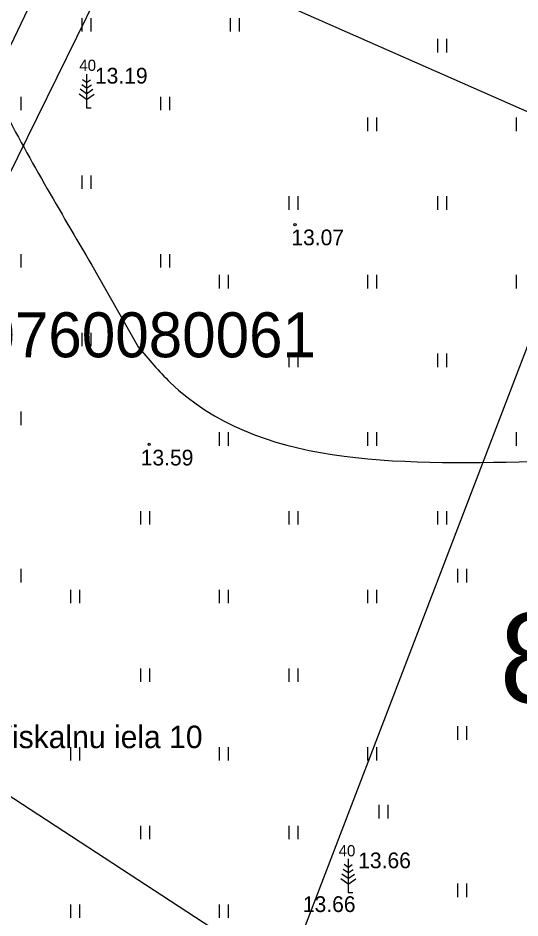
# Model space of a CAD drawing. Extents: x 503877 to 504025, y 304562 to 304725.
# Drawn here: x 503952.92 to 503975.24, y 304618.66 to 304658.69 of the extents above; entities that cross this region are included whole.
import ezdxf

# ---------------------------------------------------------------- set-up
doc = ezdxf.new("R2010")
doc.units = 0
for name, color, linetype in [('24', 7, 'Continuous'), ('APGS_VADP_ZSPR_####_#', 7, 'Continuous'), ('BUVE_EKAS_ADRS_TKST_#', 7, 'Continuous'), ('Level 1', 7, 'Continuous'), ('Level 46', 7, 'Continuous'), ('RELJ_AATZ_####_TKST_#', 7, 'Continuous'), ('RELJ_ELEM_####_####_#', 7, 'Continuous'), ('RELJ_HORZ_PAMT_####_#', 7, 'Continuous'), ('TERT_DIAM_####_TKST_#', 7, 'Continuous'), ('TERT_ELEM_####_####_#', 7, 'Continuous')]:
    doc.layers.add(name, color=color, linetype=linetype)

msp = doc.modelspace()

# ---------------------------------------------------------------- linework, layer by layer
at = {"layer": '24'}
for p, q in [((503952.592, 304664.678), (503978.978, 304653.014)), ((503978.978, 304653.014), (503960.823, 304605.633))]:
    msp.add_line(p, q, dxfattribs=at)
at = {"layer": 'APGS_VADP_ZSPR_####_#'}
msp.add_lwpolyline([(503962.091, 304677.36), (503950.94, 304654.055), (503950.749, 304653.94), (503947.69, 304653.253), (503947.598, 304653.154), (503939.904, 304637.662)], dxfattribs=at)
at = {"layer": 'Level 1'}
for p, q in [((503967.6, 304620.911), (503967.562, 304620.939)), ((503967.6, 304621.053), (503967.6, 304619.787)), ((503967.6, 304620.911), (503967.774, 304621.039)), ((503967.6, 304620.411), (503967.427, 304620.538)), ((503967.6, 304620.661), (503967.494, 304620.738)), ((503967.6, 304620.661), (503967.816, 304620.819)), ((503967.6, 304620.411), (503967.878, 304620.615)), ((503967.6, 304620.161), (503967.36, 304620.338)), ((503967.6, 304620.161), (503967.934, 304620.405)), ((503967.6, 304619.787), (503967.8, 304619.787))]:
    msp.add_line(p, q, dxfattribs=at)
at = {"layer": 'Level 46'}
msp.add_line((503980.064, 304707.607), (503941.479, 304629.359), dxfattribs=at)
at = {"layer": 'RELJ_ELEM_####_####_#'}
for centre in [(503965.239, 304649.497), (503958.753, 304639.733)]:
    msp.add_circle(centre, 0.05, dxfattribs=at)
at = {"layer": 'RELJ_HORZ_PAMT_####_#'}
for p, q in [((503956.212, 304647.7), (503958.259, 304644.072)), ((503966.227, 304615.164), (503949.188, 304626.264))]:
    msp.add_line(p, q, dxfattribs=at)
for points in [[(503952.816, 304672.072), (503952.987, 304664.738), (503952.905, 304663.502), (503952.654, 304662.245), (503952.49, 304661.612), (503952.312, 304660.984), (503952.133, 304660.355), (503951.965, 304659.719), (503951.712, 304658.5), (503951.624, 304657.887), (503951.562, 304657.273), (503951.573, 304656.693), (503951.668, 304656.113), (503951.833, 304655.556), (503952.085, 304655.015), (503956.212, 304647.7)], [(503958.259, 304644.072), (503959.691, 304642.482), (503975.774, 304638.957)]]:
    msp.add_spline(points, degree=3, dxfattribs=at)
at = {"layer": 'TERT_ELEM_####_####_#'}
for p, q in [((503955.771, 304658.087), (503955.771, 304658.687)), ((503956.171, 304658.087), (503956.171, 304658.687)), ((503962.371, 304658.087), (503962.371, 304658.687)), ((503962.771, 304658.087), (503962.771, 304658.687)), ((503971.579, 304657.162), (503971.579, 304657.762)), ((503971.979, 304657.162), (503971.979, 304657.762)), ((503955.97, 304656.192), (503955.97, 304654.692)), ((503955.97, 304655.566), (503955.754, 304655.724)), ((503955.97, 304655.816), (503955.794, 304655.944)), ((503955.97, 304655.816), (503956.144, 304655.944)), ((503955.97, 304655.566), (503956.186, 304655.724)), ((503955.97, 304655.066), (503955.638, 304655.31)), ((503955.97, 304655.316), (503955.692, 304655.52)), ((503955.97, 304655.316), (503956.248, 304655.52)), ((503955.97, 304655.066), (503956.304, 304655.31)), ((503953.071, 304654.587), (503953.071, 304655.187)), ((503959.271, 304654.587), (503959.271, 304655.187)), ((503959.671, 304654.587), (503959.671, 304655.187)), ((503955.97, 304654.692), (503956.17, 304654.692)), ((503968.479, 304653.662), (503968.479, 304654.262)), ((503968.879, 304653.662), (503968.879, 304654.262)), ((503975.079, 304653.662), (503975.079, 304654.262)), ((503955.771, 304651.087), (503955.771, 304651.687)), ((503956.171, 304651.087), (503956.171, 304651.687)), ((503964.979, 304650.162), (503964.979, 304650.762)), ((503965.379, 304650.162), (503965.379, 304650.762)), ((503971.579, 304650.162), (503971.579, 304650.762)), ((503971.979, 304650.162), (503971.979, 304650.762)), ((503953.071, 304647.587), (503953.071, 304648.187)), ((503959.271, 304647.587), (503959.271, 304648.187)), ((503959.671, 304647.587), (503959.671, 304648.187)), ((503961.879, 304646.662), (503961.879, 304647.262)), ((503962.279, 304646.662), (503962.279, 304647.262)), ((503968.479, 304646.662), (503968.479, 304647.262)), ((503968.879, 304646.662), (503968.879, 304647.262)), ((503975.079, 304646.662), (503975.079, 304647.262)), ((503955.771, 304644.087), (503955.771, 304644.687)), ((503956.171, 304644.087), (503956.171, 304644.687)), ((503964.979, 304643.162), (503964.979, 304643.762)), ((503965.379, 304643.162), (503965.379, 304643.762)), ((503971.579, 304643.162), (503971.579, 304643.762)), ((503971.979, 304643.162), (503971.979, 304643.762)), ((503953.071, 304640.587), (503953.071, 304641.187)), ((503961.879, 304639.662), (503961.879, 304640.262)), ((503962.279, 304639.662), (503962.279, 304640.262)), ((503968.479, 304639.662), (503968.479, 304640.262)), ((503968.879, 304639.662), (503968.879, 304640.262)), ((503975.079, 304639.662), (503975.079, 304640.262)), ((503958.379, 304636.162), (503958.379, 304636.762)), ((503958.779, 304636.162), (503958.779, 304636.762)), ((503964.979, 304636.162), (503964.979, 304636.762)), ((503965.379, 304636.162), (503965.379, 304636.762)), ((503971.579, 304636.162), (503971.579, 304636.762)), ((503971.979, 304636.162), (503971.979, 304636.762)), ((503953.071, 304633.587), (503953.071, 304634.187)), ((503972.471, 304633.587), (503972.471, 304634.187)), ((503972.871, 304633.587), (503972.871, 304634.187)), ((503955.279, 304632.662), (503955.279, 304633.262)), ((503955.679, 304632.662), (503955.679, 304633.262)), ((503961.879, 304632.662), (503961.879, 304633.262)), ((503962.279, 304632.662), (503962.279, 304633.262)), ((503968.479, 304632.662), (503968.479, 304633.262)), ((503968.879, 304632.662), (503968.879, 304633.262)), ((503958.379, 304629.162), (503958.379, 304629.762)), ((503958.779, 304629.162), (503958.779, 304629.762)), ((503964.979, 304629.162), (503964.979, 304629.762)), ((503965.379, 304629.162), (503965.379, 304629.762)), ((503972.471, 304626.587), (503972.471, 304627.187)), ((503972.871, 304626.587), (503972.871, 304627.187)), ((503955.279, 304625.662), (503955.279, 304626.262)), ((503955.679, 304625.662), (503955.679, 304626.262)), ((503961.879, 304625.662), (503961.879, 304626.262)), ((503962.279, 304625.662), (503962.279, 304626.262)), ((503968.479, 304625.662), (503968.479, 304626.262)), ((503968.879, 304625.662), (503968.879, 304626.262)), ((503968.971, 304623.087), (503968.971, 304623.687)), ((503969.371, 304623.087), (503969.371, 304623.687)), ((503958.379, 304622.162), (503958.379, 304622.762)), ((503958.779, 304622.162), (503958.779, 304622.762)), ((503964.979, 304622.162), (503964.979, 304622.762)), ((503965.379, 304622.162), (503965.379, 304622.762)), ((503967.6, 304621.287), (503967.6, 304619.787)), ((503967.6, 304620.911), (503967.424, 304621.039)), ((503967.6, 304620.911), (503967.774, 304621.039)), ((503967.6, 304620.411), (503967.322, 304620.615)), ((503967.6, 304620.661), (503967.384, 304620.819)), ((503967.6, 304620.661), (503967.816, 304620.819)), ((503967.6, 304620.411), (503967.878, 304620.615)), ((503967.6, 304620.161), (503967.268, 304620.405)), ((503967.6, 304620.161), (503967.934, 304620.405)), ((503972.471, 304619.587), (503972.471, 304620.187)), ((503972.871, 304619.587), (503972.871, 304620.187)), ((503967.6, 304619.787), (503967.8, 304619.787)), ((503955.279, 304618.662), (503955.279, 304619.262)), ((503955.679, 304618.662), (503955.679, 304619.262)), ((503961.879, 304618.662), (503961.879, 304619.262)), ((503962.279, 304618.662), (503962.279, 304619.262))]:
    msp.add_line(p, q, dxfattribs=at)

# ---------------------------------------------------------------- texts
at = {"layer": '24'}
for s, height, p in [('80760080061', 2, (503949.809, 304643.599)), ('80760080043', 4, (503974.335, 304628.227))]:
    msp.add_text(s, height=height, dxfattribs=at).set_placement(p)
at = {"layer": 'BUVE_EKAS_ADRS_TKST_#'}
msp.add_text('Viskalnu iela 10', height=1, dxfattribs=at).set_placement((503951.763, 304626.215))
at = {"layer": 'RELJ_AATZ_####_TKST_#'}
for s, p in [('13.19', (503956.342, 304655.775)), ('13.07', (503965.074, 304648.582)), ('13.59', (503958.378, 304638.788)), ('13.66', (503968.045, 304620.871)), ('13.66', (503965.585, 304618.925))]:
    msp.add_text(s, height=0.7, dxfattribs=at).set_placement(p)
at = {"layer": 'TERT_DIAM_####_TKST_#'}
for p in [(503955.648, 304656.337), (503967.176, 304621.401)]:
    msp.add_text('40', height=0.5, dxfattribs=at).set_placement(p)

doc.saveas('drawing.dxf')
